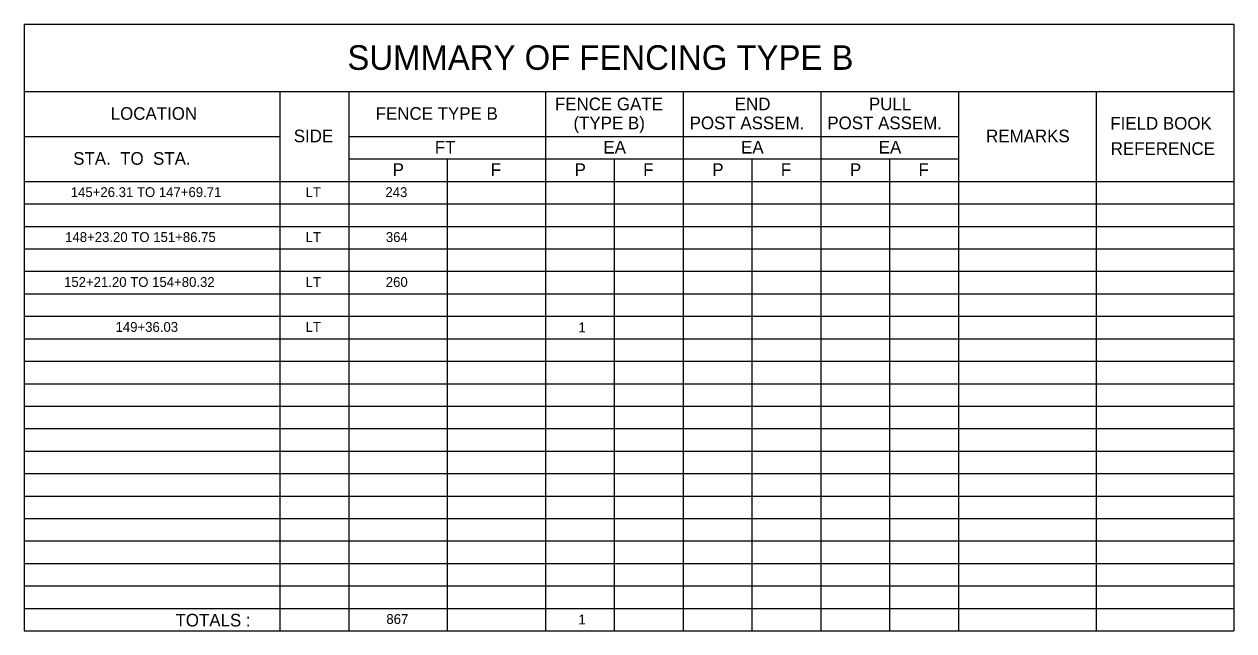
# Model space of a CAD drawing. Extents: x 0.1 to 38.9, y -11.7 to 25.8.
# Drawn here: x 8.17 to 16.53, y 21.65 to 25.85 of the extents above; entities that cross this region are included whole.
import ezdxf

# ---------------------------------------------------------------- set-up
doc = ezdxf.new("R2010")
doc.units = 0
doc.layers.add('Default', color=7, linetype='Continuous')

msp = doc.modelspace()

# ---------------------------------------------------------------- linework, layer by layer
at = {"layer": 'Default'}
for p, q in [((8.1743, 25.8462), (16.5295, 25.8462)), ((8.1743, 25.8462), (8.1743, 21.654)), ((16.5295, 25.8462), (16.5295, 21.654)), ((8.1743, 25.3804), (16.5295, 25.3804)), ((8.1743, 25.3804), (8.1743, 21.654)), ((9.9404, 25.3804), (9.9404, 21.654)), ((10.4159, 25.3804), (10.4159, 21.654)), ((11.7745, 25.3804), (11.7745, 21.654)), ((12.7255, 25.3804), (12.7255, 21.654)), ((13.6765, 25.3804), (13.6765, 21.654)), ((14.6275, 25.3804), (14.6275, 21.654)), ((15.5785, 25.3804), (15.5785, 21.654)), ((8.1743, 25.0699), (9.9404, 25.0699)), ((10.4159, 25.0699), (14.6275, 25.0699)), ((10.4159, 24.9146), (14.6275, 24.9146)), ((11.0952, 24.9146), (11.0952, 21.654)), ((12.25, 24.9146), (12.25, 21.654)), ((13.201, 24.9146), (13.201, 21.654)), ((14.152, 24.9146), (14.152, 21.654)), ((8.1743, 24.7593), (16.5295, 24.7593)), ((8.1743, 24.6041), (16.5295, 24.6041)), ((8.1743, 24.4488), (16.5295, 24.4488)), ((8.1743, 24.2935), (16.5295, 24.2935)), ((8.1743, 24.1383), (16.5295, 24.1383)), ((8.1743, 23.983), (16.5295, 23.983)), ((8.1743, 23.8277), (16.5295, 23.8277)), ((8.1743, 23.6725), (16.5295, 23.6725)), ((8.1743, 23.5172), (16.5295, 23.5172)), ((8.1743, 23.3619), (16.5295, 23.3619)), ((8.1743, 23.2067), (16.5295, 23.2067)), ((8.1743, 23.0514), (16.5295, 23.0514)), ((8.1743, 22.8961), (16.5295, 22.8961)), ((8.1743, 22.7409), (16.5295, 22.7409)), ((8.1743, 22.5856), (16.5295, 22.5856)), ((8.1743, 22.4303), (16.5295, 22.4303)), ((8.1743, 22.2751), (16.5295, 22.2751)), ((8.1743, 22.1198), (16.5295, 22.1198)), ((8.1743, 21.9645), (16.5295, 21.9645)), ((8.1743, 21.8093), (16.5295, 21.8093)), ((8.1743, 21.654), (16.5295, 21.654))]:
    msp.add_line(p, q, dxfattribs=at)

# ---------------------------------------------------------------- texts
for s, height, p in [('SUMMARY OF FENCING TYPE B', 0.16983, (10.4069, 25.5307)), ('FENCE GATE', 0.08734, (11.8402, 25.2513)), ('END', 0.08734, (13.0824, 25.2513)), ('PULL', 0.08734, (14.0091, 25.2513)), ('LOCATION', 0.08734, (8.7718, 25.1853)), ('FENCE TYPE B', 0.087337, (10.602, 25.1853)), ('(TYPE B)', 0.08734, (11.9683, 25.1202)), ('POST ASSEM.', 0.087337, (12.7709, 25.1202)), ('POST ASSEM.', 0.087337, (13.7219, 25.1202)), ('FIELD BOOK', 0.08734, (15.6763, 25.1173)), ('SIDE', 0.08734, (10.0362, 25.03)), ('REMARKS', 0.08734, (14.8184, 25.03)), ('FT', 0.08734, (11.0105, 24.9524)), ('EA', 0.08734, (12.175, 24.9524)), ('EA', 0.08734, (13.126, 24.9524)), ('EA', 0.08734, (14.077, 24.9524)), ('REFERENCE', 0.08734, (15.6792, 24.9427)), ('STA.  TO  STA.', 0.087337, (8.5127, 24.8747)), ('P', 0.0873, (10.7194, 24.7971)), ('F', 0.0873, (11.3968, 24.7971)), ('P', 0.0873, (11.9761, 24.7971)), ('F', 0.0873, (12.4497, 24.7971)), ('P', 0.0873, (12.9271, 24.7971)), ('F', 0.0873, (13.4007, 24.7971)), ('P', 0.0873, (13.8781, 24.7971)), ('F', 0.0873, (14.3517, 24.7971)), ('145+26.31 TO 147+69.71', 0.067931, (8.4959, 24.6515)), ('LT', 0.06793, (10.1178, 24.6515)), ('243', 0.06793, (10.6692, 24.6515)), ('148+23.20 TO 151+86.75', 0.067931, (8.457, 24.341)), ('LT', 0.06793, (10.1181, 24.341)), ('364', 0.06793, (10.6725, 24.341)), ('152+21.20 TO 154+80.32', 0.067931, (8.4495, 24.0305)), ('LT', 0.06793, (10.1181, 24.0305)), ('260', 0.06793, (10.672, 24.0305)), ('149+36.03', 0.06793, (8.8053, 23.7199)), ('LT', 0.06793, (10.1178, 23.7199)), ('1', 0.0679, (12.0027, 23.717)), ('TOTALS :', 0.08734, (9.2192, 21.684)), ('867', 0.06793, (10.6759, 21.7015)), ('1', 0.0679, (12.0027, 21.6986))]:
    msp.add_text(s, height=height, dxfattribs=at).set_placement(p)

doc.saveas('drawing.dxf')
